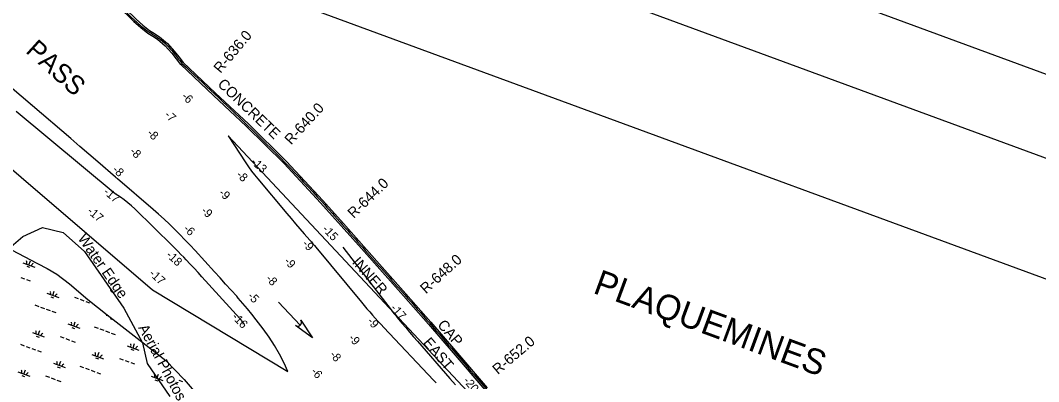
# Model space of a CAD drawing. Extents: x 3972907 to 3994831, y 172639 to 190852.
# Drawn here: x 3980022 to 3984065, y 186879 to 188313 of the extents above; entities that cross this region are included whole.
import ezdxf

# ---------------------------------------------------------------- set-up
doc = ezdxf.new("R2010")
doc.units = 0
for name, color, linetype in [('G-ANNO-NPLT', 7, 'Continuous'), ('V-ANNO-SYMB', 7, 'Continuous'), ('V-GRID-FRAM', 7, 'Continuous'), ('V-RIVR-EDGE', 7, 'Continuous'), ('V-RIVR-IDEN', 7, 'Continuous'), ('V-RIVR-JETY', 7, 'Continuous'), ('V-RIVR-RANG', 7, 'Continuous'), ('V-RIVR-RANG-IDEN', 7, 'Continuous'), ('V-STRM-FLOW', 7, 'Continuous'), ('V-TOPO-DPTH', 7, 'Continuous'), ('V-TOPO-GNAM-IDEN', 7, 'Continuous'), ('V-TOPO-MINR', 7, 'Continuous'), ('V-WETL-SWMP', 7, 'Continuous')]:
    doc.layers.add(name, color=color, linetype=linetype)

msp = doc.modelspace()

# ---------------------------------------------------------------- linework, layer by layer
at = {"layer": 'G-ANNO-NPLT'}
msp.add_lwpolyline([(3973180.8, 179237.2), (3990388.6, 172912.5), (3994557.2, 184254), (3977349.3, 190578.7)], close=True, dxfattribs=at)
at = {"layer": 'V-ANNO-SYMB'}
msp.add_lwpolyline([(3974579.2, 179056.1), (3990105.3, 173349.5), (3994058.3, 184104.4), (3978532.2, 189811), (3974579.2, 179056.1)], dxfattribs=at)
at = {"layer": 'V-GRID-FRAM'}
msp.add_lwpolyline([(3976065.4, 181215.5), (3978987, 189164.4), (3993292.9, 183906.2), (3990371.3, 175957.4), (3976065.4, 181215.5)], dxfattribs=at)
at = {"layer": 'V-RIVR-EDGE'}
msp.add_lwpolyline([(3979977.1, 187407.6), (3980031.9, 187455.1), (3980110.6, 187490.9), (3980191.7, 187471.8), (3980277.6, 187395.4), (3980432.7, 187171.2), (3980506.7, 187032.8), (3980525.8, 186951.6), (3980616.4, 186820.4)], dxfattribs=at)
at = {"layer": 'V-RIVR-JETY'}
for points in [[(3979949.7, 188810.6), (3980070.3, 188698.3), (3980223.9, 188553.4), (3980348.5, 188431.1), (3980473.1, 188308.2), (3980500.1, 188284.9), (3980528.4, 188263), (3980548.1, 188250.5), (3980567.1, 188238.1), (3980597.2, 188212), (3980624.1, 188182.6), (3980641.4, 188160.7), (3980658.8, 188138.6)], [(3979980, 188799.4), (3980078.9, 188707.4), (3980232.6, 188562.4), (3980357.3, 188440), (3980481.6, 188317.4), (3980508, 188294.6), (3980535.6, 188273.3), (3980554.9, 188261), (3980574.7, 188248.2), (3980606, 188221), (3980633.6, 188190.7), (3980651.2, 188168.4), (3980668.6, 188146.4)], [(3980659.5, 188137.9), (3980789.2, 188015.6), (3980919, 187893.3), (3981070, 187744.7), (3981214.5, 187589.5), (3981295.7, 187498.3), (3981376.9, 187407.1), (3981460.5, 187313.2), (3981544.1, 187219.3), (3981643.1, 187106.7), (3981741.2, 186993.3), (3981866.5, 186846.6)], [(3980668, 188147), (3980797.8, 188024.7), (3980927.6, 187902.3), (3981079, 187753.4), (3981223.7, 187597.9), (3981305, 187506.6), (3981386.2, 187415.4), (3981469.8, 187321.5), (3981553.4, 187227.6), (3981652.5, 187114.9), (3981750.7, 187001.5), (3981876.1, 186854.6)]]:
    msp.add_lwpolyline(points, dxfattribs=at)
for points in [[(3979098.2, 189603), (3979284.7, 189431.5), (3979614.8, 189124.3), (3979920, 188846.7), (3980228.2, 188557.9), (3980477.4, 188312.8), (3980532, 188268.2), (3980570.9, 188243.1), (3980628.8, 188186.6), (3980663.7, 188142.5)], [(3980663.7, 188142.5), (3980923.3, 187897.8), (3981219.1, 187593.7), (3981381.5, 187411.2), (3981548.8, 187223.5), (3981746, 186997.4), (3981995.9, 186703.1), (3982288, 186350.3), (3982495.8, 186079.5), (3982762.8, 185654.7), (3982971, 185292.4), (3983111.2, 185037.5), (3983200, 184881.8), (3983229.9, 184826.4)]]:
    msp.add_spline(points, degree=3, dxfattribs=at)
at = {"layer": 'V-STRM-FLOW'}
msp.add_line((3981047.2, 187194.1), (3981133.9, 187103.7), dxfattribs=at)
msp.add_lwpolyline([(3981136.1, 187123.1), (3981182.9, 187052.6), (3981114.4, 187102.4), (3981115.7, 187101.5), (3981117, 187100.9), (3981117.5, 187100.6), (3981118, 187100.4), (3981118.6, 187100.2), (3981119.2, 187100), (3981119.7, 187099.9), (3981120.4, 187099.8), (3981121.2, 187099.6), (3981121.6, 187099.6), (3981122.2, 187099.5), (3981122.9, 187099.5), (3981123.5, 187099.5), (3981124.1, 187099.5), (3981124.5, 187099.5), (3981124.9, 187099.6), (3981125.5, 187099.6), (3981126, 187099.7), (3981126.5, 187099.8), (3981126.9, 187099.9), (3981127.5, 187100), (3981128, 187100.2), (3981128.5, 187100.4), (3981129, 187100.6), (3981129.4, 187100.7), (3981129.8, 187100.9), (3981130.1, 187101.1), (3981130.6, 187101.3), (3981131, 187101.5), (3981131.4, 187101.8), (3981131.8, 187102.1), (3981132.2, 187102.3), (3981132.6, 187102.6), (3981132.9, 187102.9), (3981133.4, 187103.3), (3981133.9, 187103.7), (3981134, 187103.9), (3981134.3, 187104.1), (3981134.5, 187104.3), (3981134.7, 187104.6), (3981135, 187104.9), (3981135.2, 187105.1), (3981135.4, 187105.4), (3981135.6, 187105.7), (3981135.8, 187106), (3981136, 187106.3), (3981136.2, 187106.5), (3981136.5, 187107.1), (3981136.7, 187107.4), (3981136.8, 187107.6), (3981137, 187108), (3981137.2, 187108.3), (3981137.3, 187108.7), (3981137.5, 187109.1), (3981137.6, 187109.5), (3981137.8, 187109.8), (3981137.8, 187110.1), (3981138, 187110.4), (3981138.1, 187110.7), (3981138.2, 187111.1), (3981138.2, 187111.5), (3981138.3, 187111.9), (3981138.4, 187112.4), (3981138.5, 187112.8), (3981138.5, 187113.2), (3981138.5, 187113.6), (3981138.6, 187113.9), (3981138.6, 187114.3), (3981138.6, 187114.8), (3981138.6, 187114.8), (3981138.6, 187115.1), (3981138.6, 187115.4), (3981138.5, 187115.7), (3981138.5, 187116.1), (3981138.5, 187116.5), (3981138.4, 187116.8), (3981138.4, 187117.2), (3981138.3, 187117.5), (3981138.3, 187117.8), (3981138.2, 187118.2), (3981138.1, 187118.6), (3981138, 187118.9), (3981137.9, 187119.1), (3981137.9, 187119.3), (3981137.8, 187119.6), (3981137.7, 187119.9), (3981137.6, 187120.2), (3981137.5, 187120.5), (3981137.3, 187120.8), (3981137.2, 187121.2), (3981137.1, 187121.4), (3981136.9, 187121.7), (3981136.7, 187122.1), (3981136.5, 187122.4), (3981136.3, 187122.7), (3981136.2, 187122.9), (3981136.1, 187123)], close=True, dxfattribs=at)
at = {"layer": 'V-TOPO-DPTH'}
for points in [[(3978990.6, 188578.5), (3980546.8, 187243.1), (3981084.2, 186920)], [(3981084.2, 186920), (3981069.5, 186952), (3981051.4, 186987.8), (3981031.8, 187022.7), (3981010, 187056.3), (3980986.5, 187088.9), (3980958.9, 187124.7), (3980941.6, 187146.6), (3980924.1, 187168.3), (3980906.1, 187189.6), (3980887.7, 187210.6), (3980881.3, 187217.9), (3980859.5, 187242.3), (3980837.5, 187266.7), (3980815.5, 187290.9), (3980793.4, 187315.1), (3980715.9, 187399.4), (3980696, 187420.8), (3980675.8, 187442), (3980655.4, 187463), (3980634.9, 187483.8), (3980613.9, 187504.2), (3980592.7, 187524.3), (3980571, 187543.9), (3980549, 187563.1), (3980408.5, 187683.7), (3980405.3, 187686.3), (3980403.2, 187688.1), (3980401.1, 187689.8), (3980400, 187690.7), (3980330.4, 187751.1), (3980294.6, 187782.1), (3980258.6, 187813), (3980222.6, 187843.9), (3980186.5, 187874.7), (3979782.7, 188218.5)], [(3982050, 186570.6), (3980847, 187854.8), (3980917.3, 187747.8), (3980928.4, 187731.4), (3980940, 187715.2), (3980952.1, 187699.5), (3980964.6, 187684.1), (3981080, 187546.4), (3981097.1, 187526.2), (3981114.2, 187506.2), (3981131.5, 187486.3), (3981148.9, 187466.4), (3981171.8, 187440.5), (3981177.8, 187433.7), (3981183.8, 187426.8), (3981189.7, 187419.9), (3981195.5, 187412.9), (3981376.9, 187194.6), (3981387.7, 187181.7), (3981398.6, 187168.8), (3981409.5, 187156.1), (3981420.6, 187143.4), (3981431.7, 187130.8), (3981443, 187118.3), (3981454.4, 187105.9), (3981465.8, 187093.6), (3981663, 186884.8), (3981673.2, 186873.9)]]:
    msp.add_lwpolyline(points, dxfattribs=at)
at = {"layer": 'V-TOPO-MINR'}
for points in [[(3981084.2, 186920), (3981069.5, 186952), (3981051.4, 186987.8), (3981031.8, 187022.7), (3981010, 187056.3), (3980986.5, 187088.9), (3980958.9, 187124.7), (3980941.6, 187146.6), (3980924.1, 187168.3), (3980906.1, 187189.6), (3980887.7, 187210.6), (3980881.3, 187217.9), (3980859.5, 187242.3), (3980837.5, 187266.7), (3980815.5, 187290.9), (3980793.4, 187315.1), (3980715.9, 187399.4), (3980696, 187420.8), (3980675.8, 187442), (3980655.4, 187463), (3980634.9, 187483.8), (3980613.9, 187504.2), (3980592.7, 187524.3), (3980571, 187543.9), (3980549, 187563.1), (3980408.5, 187683.7), (3980405.3, 187686.3), (3980403.2, 187688.1), (3980401.1, 187689.8), (3980400, 187690.7), (3980330.4, 187751.1), (3980294.6, 187782.1), (3980258.6, 187813), (3980222.6, 187843.9), (3980186.5, 187874.7), (3979782.7, 188218.5)], [(3980907.6, 187107.9), (3980908.1, 187109.4), (3980907.8, 187111.1), (3980906.5, 187114.3), (3980905.5, 187115.8), (3980900.2, 187122.5), (3980898.6, 187124.5), (3980896.9, 187126.5), (3980895.3, 187128.4), (3980893.6, 187130.4), (3980743.1, 187295.7), (3980727.7, 187312.6), (3980712.1, 187329.3), (3980696.5, 187346), (3980680.8, 187362.6), (3980670.8, 187373.2), (3980660, 187384.4), (3980649.1, 187395.5), (3980638.1, 187406.5), (3980627.1, 187417.4), (3980476.6, 187564.5), (3980463, 187577.1), (3980449.1, 187589.2), (3980434.5, 187600.5), (3980419.5, 187611.2), (3980399.4, 187625), (3980006.3, 187952.1)], [(3980847, 187854.8), (3980917.3, 187747.8), (3980928.4, 187731.4), (3980940, 187715.2), (3980952.1, 187699.5), (3980964.6, 187684.1), (3981080, 187546.4), (3981097.1, 187526.2), (3981114.2, 187506.2), (3981131.5, 187486.3), (3981148.9, 187466.4), (3981171.8, 187440.5), (3981177.8, 187433.7), (3981183.8, 187426.8), (3981189.7, 187419.9), (3981195.5, 187412.9), (3981376.9, 187194.6), (3981387.7, 187181.7), (3981398.6, 187168.8), (3981409.5, 187156.1), (3981420.6, 187143.4), (3981431.7, 187130.8), (3981443, 187118.3), (3981454.4, 187105.9), (3981465.8, 187093.6), (3981663, 186884.8), (3981673.2, 186873.9)], [(3981303.1, 187412.4), (3981494.6, 187163.6), (3981500.5, 187156), (3981506.4, 187148.6), (3981512.5, 187141.2), (3981518.6, 187133.8), (3981537, 187111.9), (3981552.5, 187093.7), (3981568, 187075.5), (3981583.6, 187057.5), (3981599.2, 187039.4), (3981728.1, 186891.9), (3981750.3, 186866.3)]]:
    msp.add_lwpolyline(points, dxfattribs=at)
at = {"layer": 'V-WETL-SWMP'}
for p, q in [((3980032.8, 187351.1), (3980079.7, 187333.9)), ((3980056.2, 187342.5), (3980062.4, 187359.4)), ((3980047.9, 187337.3), (3980059.2, 187333.2)), ((3980024.4, 187292.7), (3980039.4, 187287.2)), ((3980046.9, 187284.4), (3980061.9, 187278.9)), ((3980127.5, 187230), (3980174.5, 187212.8)), ((3980151, 187221.4), (3980157.2, 187238.3)), ((3980142.7, 187216.2), (3980154, 187212.1)), ((3980237.4, 187214.4), (3980252.4, 187208.9)), ((3980259.9, 187206.1), (3980275, 187200.6)), ((3980282.5, 187197.8), (3980297.5, 187192.3)), ((3980080.2, 187183.5), (3980095.2, 187178)), ((3980102.7, 187175.2), (3980117.7, 187169.7)), ((3980125.2, 187166.9), (3980140.2, 187161.4)), ((3980147.7, 187158.7), (3980162.7, 187153.1)), ((3980210.9, 187108.4), (3980257.9, 187091.2)), ((3980234.4, 187099.8), (3980240.6, 187116.7)), ((3980363.1, 187143.5), (3980373.1, 187139.8)), ((3980378.3, 187129.7), (3980389.5, 187125.5)), ((3980070.2, 187073.9), (3980117.1, 187056.7)), ((3980093.6, 187065.3), (3980099.8, 187082.2)), ((3980226.1, 187094.6), (3980237.4, 187090.5)), ((3980315.7, 187096.9), (3980330.7, 187091.4)), ((3980338.2, 187088.6), (3980353.2, 187083.1)), ((3980360.8, 187080.4), (3980375.8, 187074.8)), ((3980383.3, 187072.1), (3980398.3, 187066.6)), ((3980022.8, 187027.4), (3980037.8, 187021.9)), ((3980085.3, 187060.1), (3980096.6, 187056)), ((3980180, 187058.3), (3980195.1, 187052.7)), ((3980202.6, 187050), (3980217.6, 187044.5)), ((3980225.1, 187041.7), (3980240.1, 187036.2)), ((3980469.9, 187013.2), (3980476.2, 187030.1)), ((3980045.3, 187019.1), (3980060.3, 187013.6)), ((3980067.8, 187010.8), (3980082.8, 187005.3)), ((3980090.3, 187002.5), (3980105.4, 186997)), ((3980305.7, 186987.3), (3980352.6, 186970.1)), ((3980329.2, 186978.7), (3980335.4, 186995.6)), ((3980446.5, 187021.8), (3980493.4, 187004.6)), ((3980461.6, 187008), (3980472.9, 187003.9)), ((3980153.5, 186952.3), (3980200.5, 186935)), ((3980177, 186943.7), (3980183.2, 186960.5)), ((3980320.9, 186973.5), (3980332.1, 186969.4)), ((3980415.6, 186971.7), (3980430.6, 186966.2)), ((3980438.1, 186963.4), (3980453.1, 186957.9)), ((3980460.6, 186955.1), (3980475.7, 186949.6)), ((3980012.8, 186917.8), (3980059.7, 186900.5)), ((3980036.2, 186909.2), (3980042.4, 186926.1)), ((3980168.7, 186938.5), (3980180, 186934.3)), ((3980258.3, 186940.8), (3980273.3, 186935.3)), ((3980280.8, 186932.5), (3980295.9, 186927)), ((3980303.4, 186924.2), (3980318.4, 186918.7)), ((3980325.9, 186916), (3980340.9, 186910.4)), ((3980564.7, 186892.1), (3980570.9, 186909)), ((3980027.9, 186904), (3980039.2, 186899.9)), ((3980122.6, 186902.1), (3980137.7, 186896.6)), ((3980145.2, 186893.9), (3980160.2, 186888.3)), ((3980167.7, 186885.6), (3980182.7, 186880.1)), ((3980541.3, 186900.8), (3980588.2, 186883.5)), ((3980556.4, 186887), (3980567.7, 186882.8)), ((3980651.1, 186885.1), (3980666.1, 186879.6))]:
    msp.add_line(p, q, dxfattribs=at)
msp.add_lwpolyline([(3979987.8, 187401.9), (3980090.6, 187348.8), (3980128.6, 187327.7), (3980167.4, 187305.6), (3980217.2, 187267.7), (3980289.6, 187205.1), (3980367.6, 187144.1), (3980486.5, 187051.9), (3980599.3, 186963.4), (3980673.2, 186887.1), (3980767.5, 186776)], dxfattribs=at)
for centre, start, end in [((3980030.4, 187352.2), 339.0473, 20.5909), ((3980082.2, 187333.2), 119.0473, 160.5909), ((3980125.2, 187231.2), 339.0473, 20.5909), ((3980177, 187212.1), 119.0473, 160.5909), ((3980208.6, 187109.5), 339.0473, 20.5909), ((3980067.8, 187075), 339.0473, 20.5909), ((3980119.6, 187056), 119.0473, 160.5909), ((3980260.4, 187090.5), 119.0473, 160.5909), ((3980444.1, 187023), 339.0473, 20.5909), ((3980303.3, 186988.5), 339.0473, 20.5909), ((3980496, 187003.9), 119.0473, 160.5909), ((3980151.2, 186953.4), 339.0473, 20.5909), ((3980203, 186934.3), 119.0473, 160.5909), ((3980355.2, 186969.4), 119.0473, 160.5909), ((3980010.4, 186918.9), 339.0473, 20.5909), ((3980062.2, 186899.9), 119.0473, 160.5909), ((3980538.9, 186901.9), 339.0473, 20.5909), ((3980590.7, 186882.8), 119.0473, 160.5909)]:
    msp.add_arc(centre, 17.6, start, end, dxfattribs=at)

# ---------------------------------------------------------------- texts
at = {"layer": 'V-RIVR-IDEN'}
for s, height, rotation, p in [('PASS', 75, 317.8712, (3980039.9, 188187.8)), ('CONCRETE', 42, 316.3292, (3980802.5, 188056.2)), ('Water Edge', 42, 305.0624, (3980248.3, 187447.7)), ('INNER', 42, 311.4173, (3981337, 187351.3)), ('CAP', 42, 310.8911, (3981675.8, 187102.9)), ('Aerial Photos', 42, 298.2609, (3980489.3, 187093.4)), ('EAST', 42, 310.5467, (3981618.7, 187032.5))]:
    msp.add_text(s, height=height, rotation=rotation, dxfattribs=at).set_placement(p)
at = {"layer": 'V-RIVR-RANG'}
for s, rotation, p in [('-6', 316.8472, (3980660, 188007.9)), ('-7', 316.8472, (3980592.1, 187934.3)), ('-8', 316.8472, (3980522.6, 187862.5)), ('-8', 316.8472, (3980454, 187789.7)), ('-13', 317.3683, (3980935.3, 187748.1)), ('-8', 316.8472, (3980385.4, 187716.9)), ('-8', 317.5048, (3980877.3, 187696.4)), ('-17', 319.8083, (3980349.6, 187628.1)), ('-9', 317.5048, (3980807.5, 187624.8)), ('-17', 319.8083, (3980285.2, 187551.6)), ('-9', 317.5048, (3980737.5, 187553.5)), ('-6', 317.5048, (3980667.3, 187482.3)), ('-15', 313.8583, (3981218.8, 187481.9)), ('-9', 314.0037, (3981139.3, 187423.5)), ('-18', 317.3683, (3980598.5, 187378.5)), ('-9', 314.0037, (3981067.2, 187354.4)), ('-17', 317.3683, (3980531.1, 187304.6)), ('-8', 314.0037, (3980994.6, 187285.4)), ('-5', 314.0037, (3980922, 187216.6)), ('-17', 311.9083, (3981489.5, 187169.5)), ('-16', 313.8583, (3980859.7, 187134)), ('-9', 312.0462, (3981397.6, 187117.3)), ('-9', 312.0462, (3981323, 187050.6)), ('-8', 312.0462, (3981248.2, 186984.3)), ('-6', 312.0462, (3981173.8, 186917.4)), ('-20', 310.1083, (3981778.7, 186882))]:
    msp.add_text(s, height=33.5, rotation=rotation, dxfattribs=at).set_placement(p)
at = {"layer": 'V-RIVR-RANG-IDEN'}
for s, rotation, p in [('R-636.0', 49.9628, (3980817.3, 188100.6)), ('R-640.0', 47.5181, (3981097.6, 187816.8)), ('R-644.0', 44.0165, (3981345.9, 187524.8)), ('R-648.0', 42.0518, (3981632.6, 187225.7)), ('R-652.0', 40.2416, (3981918.5, 186905.1))]:
    msp.add_text(s, height=41.5, rotation=rotation, dxfattribs=at).set_placement(p)
at = {"layer": 'V-TOPO-GNAM-IDEN'}
msp.add_text('PLAQUEMINES', height=100, rotation=339.7963, dxfattribs=at).set_placement((3982292.1, 187232.3))

doc.saveas('drawing.dxf')
